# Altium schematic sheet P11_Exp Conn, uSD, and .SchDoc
size 386 x 246 mm
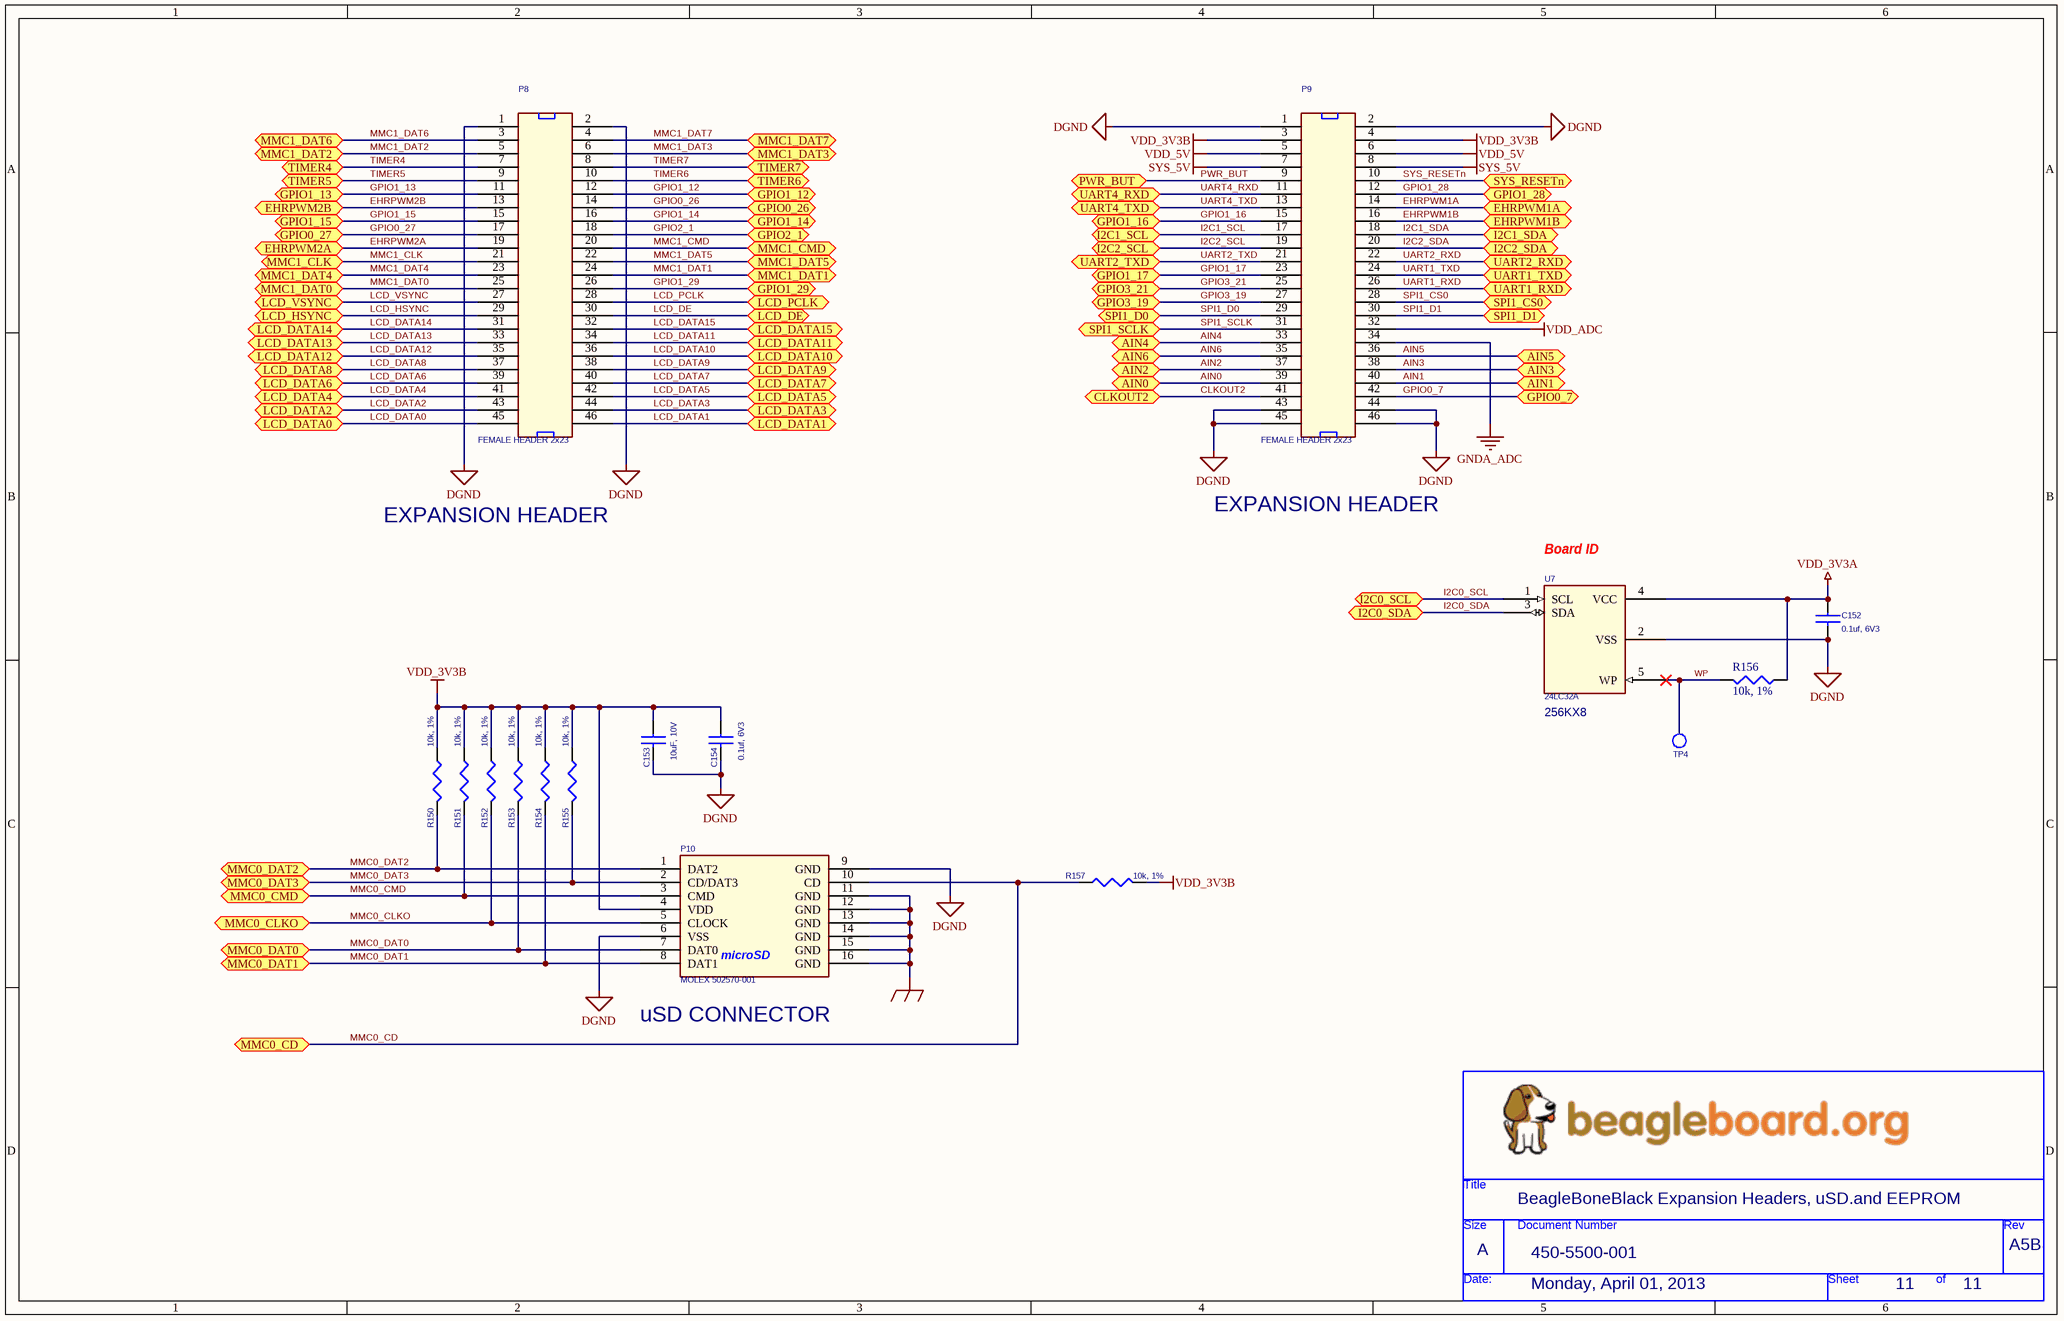
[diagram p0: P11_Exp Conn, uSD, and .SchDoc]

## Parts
*  Page Create Date: Monday, April 01, 2013  Doc: 450-5500-001  RevCode: A5B  Title: BeagleBoneBlack Expansion Headers, uSD.and EEPROM  Page Size: A  Page Number: 11  (hidden comment: BeagleBoard_org)  (graphical)
C152  0.1uf, 6V3  [402]
C153  10uF, 10V  [805]
C154  0.1uf, 6V3  [402]
P8  FEMALE HEADER 2x23  [HEADER23X2]
P9  FEMALE HEADER 2x23  [HEADER23X2]
P10  MOLEX 502570-001  [SD-MICRO-SCHA5B0300]
R150  10k, 1%  [402]
R151  10k, 1%  [402]
R152  10k, 1%  [402]
R153  10k, 1%  [402]
R154  10k, 1%  [402]
R155  10k, 1%  [402]
R156  10k, 1%  [402]
R157  10k, 1%  [402]
TP4  TESTPT1  [tp1-8040]  (value not drawn)  (no BOM)
U7  24LC32A  [SOT23-5]

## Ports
AIN0, AIN1, AIN2, AIN3, AIN4, AIN5, AIN6, CLKOUT2, EHRPWM1A, EHRPWM1B, EHRPWM2A, EHRPWM2B, GPIO0_7, GPIO0_26, GPIO0_27, GPIO1_12, GPIO1_13, GPIO1_14, GPIO1_15, GPIO1_16, GPIO1_17, GPIO1_28, GPIO1_29, GPIO2_1, GPIO3_19, GPIO3_21, I2C0_SCL, I2C0_SDA, I2C1_SCL, I2C1_SDA, I2C2_SCL, I2C2_SDA, LCD_DATA0, LCD_DATA1, LCD_DATA2, LCD_DATA3, LCD_DATA4, LCD_DATA5, LCD_DATA6, LCD_DATA7, LCD_DATA8, LCD_DATA9, LCD_DATA10, LCD_DATA11, LCD_DATA12, LCD_DATA13, LCD_DATA14, LCD_DATA15, LCD_DE, LCD_HSYNC, LCD_PCLK, LCD_VSYNC, MMC0_CD, MMC0_CLKO, MMC0_CMD, MMC0_DAT0, MMC0_DAT1, MMC0_DAT2, MMC0_DAT3, MMC1_CLK, MMC1_CMD, MMC1_DAT0, MMC1_DAT1, MMC1_DAT2, MMC1_DAT3, MMC1_DAT4, MMC1_DAT5, MMC1_DAT6, MMC1_DAT7, PWR_BUT, SPI1_CS0, SPI1_D0, SPI1_D1, SPI1_SCLK, SYS_RESETn, TIMER4, TIMER5, TIMER6, TIMER7, UART1_RXD, UART1_TXD, UART2_RXD, UART2_TXD, UART4_RXD, UART4_TXD

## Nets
DGND: C152.2 C153.2 C154.2 P8.1 P8.2 P9.1 P9.2 P9.43 P9.44 P9.45 P9.46 P10.6(VSS) P10.9(GND) U7.2(VSS)
GND_EARTH: P10.11(GND) P10.12(GND) P10.13(GND) P10.14(GND) P10.15(GND) P10.16(GND)
GNDA_ADC: P9.34
SYS_5V: P9.7 P9.8
VDD_3V3A: C152.1 R156.1 U7.4(VCC)
VDD_3V3B: C153.1 C154.1 P9.3 P9.4 P10.4(VDD) R150.1 R151.1 R152.1 R153.1 R154.1 R155.1 R157.2
VDD_5V: P9.5 P9.6
VDD_ADC: P9.32
AIN0: P9.39 ; port AIN0
AIN1: P9.40 ; port AIN1
AIN2: P9.37 ; port AIN2
AIN3: P9.38 ; port AIN3
AIN4: P9.33 ; port AIN4
AIN5: P9.36 ; port AIN5
AIN6: P9.35 ; port AIN6
CLKOUT2: P9.41 ; port CLKOUT2
EHRPWM1A: P9.14 ; port EHRPWM1A
EHRPWM1B: P9.16 ; port EHRPWM1B
EHRPWM2A: P8.19 ; port EHRPWM2A
EHRPWM2B: P8.13 ; port EHRPWM2B
GPIO0_7: P9.42 ; port GPIO0_7
GPIO0_26: P8.14 ; port GPIO0_26
GPIO0_27: P8.17 ; port GPIO0_27
GPIO1_12: P8.12 ; port GPIO1_12
GPIO1_13: P8.11 ; port GPIO1_13
GPIO1_14: P8.16 ; port GPIO1_14
GPIO1_15: P8.15 ; port GPIO1_15
GPIO1_16: P9.15 ; port GPIO1_16
GPIO1_17: P9.23 ; port GPIO1_17
GPIO1_28: P9.12 ; port GPIO1_28
GPIO1_29: P8.26 ; port GPIO1_29
GPIO2_1: P8.18 ; port GPIO2_1
GPIO3_19: P9.27 ; port GPIO3_19
GPIO3_21: P9.25 ; port GPIO3_21
I2C0_SCL: U7.1(SCL) ; port I2C0_SCL
I2C0_SDA: U7.3(SDA) ; port I2C0_SDA
I2C1_SCL: P9.17 ; port I2C1_SCL
I2C1_SDA: P9.18 ; port I2C1_SDA
I2C2_SCL: P9.19 ; port I2C2_SCL
I2C2_SDA: P9.20 ; port I2C2_SDA
LCD_DATA0: P8.45 ; port LCD_DATA0
LCD_DATA1: P8.46 ; port LCD_DATA1
LCD_DATA2: P8.43 ; port LCD_DATA2
LCD_DATA3: P8.44 ; port LCD_DATA3
LCD_DATA4: P8.41 ; port LCD_DATA4
LCD_DATA5: P8.42 ; port LCD_DATA5
LCD_DATA6: P8.39 ; port LCD_DATA6
LCD_DATA7: P8.40 ; port LCD_DATA7
LCD_DATA8: P8.37 ; port LCD_DATA8
LCD_DATA9: P8.38 ; port LCD_DATA9
LCD_DATA10: P8.36 ; port LCD_DATA10
LCD_DATA11: P8.34 ; port LCD_DATA11
LCD_DATA12: P8.35 ; port LCD_DATA12
LCD_DATA13: P8.33 ; port LCD_DATA13
LCD_DATA14: P8.31 ; port LCD_DATA14
LCD_DATA15: P8.32 ; port LCD_DATA15
LCD_DE: P8.30 ; port LCD_DE
LCD_HSYNC: P8.29 ; port LCD_HSYNC
LCD_PCLK: P8.28 ; port LCD_PCLK
LCD_VSYNC: P8.27 ; port LCD_VSYNC
MMC0_CD: P10.10(CD) R157.1 ; port MMC0_CD
MMC0_CLKO: P10.5(CLOCK) R152.2 ; port MMC0_CLKO
MMC0_CMD: P10.3(CMD) R151.2 ; port MMC0_CMD
MMC0_DAT0: P10.7(DAT0) R153.2 ; port MMC0_DAT0
MMC0_DAT1: P10.8(DAT1) R154.2 ; port MMC0_DAT1
MMC0_DAT2: P10.1(DAT2) R150.2 ; port MMC0_DAT2
MMC0_DAT3: P10.2(CD/DAT3) R155.2 ; port MMC0_DAT3
MMC1_CLK: P8.21 ; port MMC1_CLK
MMC1_CMD: P8.20 ; port MMC1_CMD
MMC1_DAT0: P8.25 ; port MMC1_DAT0
MMC1_DAT1: P8.24 ; port MMC1_DAT1
MMC1_DAT2: P8.5 ; port MMC1_DAT2
MMC1_DAT3: P8.6 ; port MMC1_DAT3
MMC1_DAT4: P8.23 ; port MMC1_DAT4
MMC1_DAT5: P8.22 ; port MMC1_DAT5
MMC1_DAT6: P8.3 ; port MMC1_DAT6
MMC1_DAT7: P8.4 ; port MMC1_DAT7
PWR_BUT: P9.9 ; port PWR_BUT
SPI1_CS0: P9.28 ; port SPI1_CS0
SPI1_D0: P9.29 ; port SPI1_D0
SPI1_D1: P9.30 ; port SPI1_D1
SPI1_SCLK: P9.31 ; port SPI1_SCLK
SYS_RESETn: P9.10 ; port SYS_RESETn
TIMER4: P8.7 ; port TIMER4
TIMER5: P8.9 ; port TIMER5
TIMER6: P8.10 ; port TIMER6
TIMER7: P8.8 ; port TIMER7
UART1_RXD: P9.26 ; port UART1_RXD
UART1_TXD: P9.24 ; port UART1_TXD
UART2_RXD: P9.22 ; port UART2_RXD
UART2_TXD: P9.21 ; port UART2_TXD
UART4_RXD: P9.11 ; port UART4_RXD
UART4_TXD: P9.13 ; port UART4_TXD
WP: R156.2 TP4.1(TP) U7.5(WP)

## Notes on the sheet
- EXPANSION HEADER
- (near U7) Board ID
- (near U7) 256KX8
- (near P10) uSD CONNECTOR

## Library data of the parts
C152 C154 = CAP_0.1uF_X7R_16V_10% 0402: CAP CER 0.1UF 6.3V 10% X5R 0402; Manufacturer: TDK Corporation; Manufacturer Part Number: C1005X5R0J104K050BA; Capacitance: 0.1µF
C153 = CAP_10uF_Y5V_10V_10%_0805: CAP CER 10UF 10V Y5V 0805; Manufacturer: TDK Corporation; Manufacturer Part Number: C2012Y5V1A106Z; Capacitance: 10µF; Temperature Coefficient: Y5V (F); Tolerance: -20%, +80%
P8 P9 = HDR_46_F_2_0.1_0.1: CONN HEADER FMAL 46PS.1" DL GOLD; Manufacturer: Sullins Connector Solutions; Manufacturer Part Number: PPPC232LFBN-RC; Number of Positions: 46; Number of Positions Loaded: All; Pitch: 0.100" (2.54mm)
P10 = microSD_CONN_2: CONN MICRO SD R/A PUSH-PUSH SMD; Manufacturer: Molex Inc; Manufacturer Part Number: 5025700893; Card Type: Secure Digital - microSD™ TransFlash; Number of Positions: 10 (8 + 2); Connector Type: Connector and Ejector; Insertion, Removal Method: Push In, Push Out
R150-R157 = RES_10K_1/16W_1%_0402: RES 10K OHM 1/16W 5% 0402 SMD; Manufacturer: Rohm Semiconductor; Manufacturer Part Number: MCR01MZPJ103; Power (Watts): 0.063W, 1/16W; Temperature Coefficient: ±200ppm/°C
U7 = 24LC32A: IC EEPROM 32KBIT 400KHZ SOT23-5; Manufacturer: Microchip Technology; Manufacturer Part Number: 24LC32AT-I/OT; Format - Memory: EEPROMs - Serial; Memory Size: 32K (4K x 8); Interface: I²C, 2-Wire Serial; Voltage - Supply: 2.5 V ~ 5.5 V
